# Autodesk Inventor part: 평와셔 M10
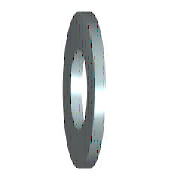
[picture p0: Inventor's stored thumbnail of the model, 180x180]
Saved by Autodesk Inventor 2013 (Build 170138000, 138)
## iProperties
IsCustomPart: 1
Created: 2012-02
Part Number: 평와셔 M10
Material: 스테인리스강
Description: 평면 와셔 - 일반 시리즈 - 제품 등급 A
Document SubType Name: Modeling
Standard: ISO 7089
Designer: mdu-01
Standard Revision: Second edition 2000-06-01
Standards Organization: ISO
Language: ko-KR
Size Designation: 10 - 140 HV
Categories: <MemberInstance><Categories><Category DisplayName="조임쇠" InternalName="e4da775c-781d-43d5-af7c-5136215cf5a6" Mnemonic="FSTN"><Category DisplayName="와셔" InternalN
Density: 8.08 g/cm^3
Author: mdu-01
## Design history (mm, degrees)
sketch "스케치"
  geometry: C1 r 10 at (0, 0); C2 r 5.25 at (0, 0); 1 further point
  constraints: 2 centre point, 2 coincident
  dimensions: "d0" = 10.5 diameter of C2 (= SD1); "d1" = 20 diameter of C1 (= SD2)
extrude "본체" new body sketch "스케치" distance "d2" = 2 (= SD); taper "d3" = 0 deg
workaxis "Work Axis1"
workplane "Work Plane1"
body "Solid1"
other parameters: "SD1" = 10.5 [user parameter; used in 1 equation term], "SD2" = 20 [user parameter; used in 1 equation term], "SD" = 2 [user parameter; used in 1 equation term], "d4" = 0, "d5" = 0, "d6" = 0, "d7" = 0
